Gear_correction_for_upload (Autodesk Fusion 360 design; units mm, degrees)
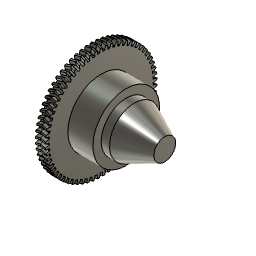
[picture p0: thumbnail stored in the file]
derived_base_feature "Derived Base Feature1"
derived_base_feature "Derived Base Feature2" bodies "Gear_roll_holder"
derived_base_feature "Derived Base Feature1" bodies "Body1"
derived_base_feature "Derived Base Feature1" bodies "Body1"
derived_base_feature "Derived Base Feature1" bodies "S2_L_Pin"
sketch "Sketch1" plane through (0, 0, 0) normal (0, 0, 1) x axis (1, 0, 0)
  line L1 (-12, -33.5) -> (-12, 33.5)
  line L2 (3, 32) -> (3, -32)
  vertical L1
  vertical L2
sketch "Sketch1" plane through (0, 0, 0) normal (0, 0, 1) x axis (1, 0, 0)
  curve K1 (33.4964, -0.4902) -> (31.4518, -0.9347)
  curve K2 (33.4964, 0.4902) -> (31.4518, 0.9347)
  curve K3 (31.4518, -0.9347) -> (31.4509, -0.9347)
  curve K4 (31.4518, 0.9347) -> (31.4509, 0.9347)
  line L1 (31.4509, -0.9347) -> (0, 0)
  line L2 (31.4509, 0.9347) -> (0, 0)
  arc A1 centre (0, 0) radius 33.5 clockwise from (33.4964, 0.4902) to (33.4964, -0.4902)
sketch "Sketch2" plane through (0, 0, 0) normal (0, 0, 1) x axis (1, 0, 0)
  circle C1 centre (0, 0) radius 31.25
extrude "Extrude1" new body sketch "Sketch2" along normal blind 6 bodies "Gear_RH_65T_Wrong"
extrude "Extrude2" new body sketch "Sketch1" along normal blind 6
circular_pattern "C-Pattern1" countU 65 TotalAngle 360
combine "Combine1"
sketch "Sketch3" plane through (0, 0, 0) normal (0, 0, 1) x axis (1, 0, 0)
  curve K1 (51.2476, 0) -> (0, 0)
  curve K2 (51.2476, 3) -> (51.2476, 0)
  curve K3 (0, 3) -> (51.2476, 3)
  curve K4 (0, 0) -> (0, 3)
  perpendicular K1 K2
  parallel K1 K3
  parallel K2 K4
position "Position2"
sketch "Sketch2" plane through (0, 0, 0) normal (0, 1, 0) x axis (0, 0, 1)
  line L1 (37.12, -11) -> (104.1, -12)
  line L2 (38.6, 3) -> (102.6, 3)
  horizontal L2
sketch "Sketch1" plane through (0, 0, 0) normal (0, 0, 1) x axis (1, 0, 0)
  curve K1 (32.4963, -0.4892) -> (30.4833, -0.9294)
  curve K2 (32.4963, 0.4892) -> (30.4833, 0.9294)
  curve K3 (30.4833, -0.9294) -> (30.4825, -0.9293)
  curve K4 (30.4833, 0.9294) -> (30.4825, 0.9293)
  line L1 (30.4825, -0.9293) -> (0, 0)
  line L2 (30.4825, 0.9293) -> (0, 0)
  line L3 (0, 0) -> (0, 0)
  line L4 (0, 0) -> (0, 0)
  arc A1 centre (0, 0) radius 32.5 clockwise from (32.4963, 0.4892) to (32.4963, -0.4892)
sketch "Sketch2" plane through (0, 0, 0) normal (0, 0, 1) x axis (1, 0, 0)
  circle C1 centre (0, 0) radius 30.25
extrude "Extrude1" new body sketch "Sketch2" along normal blind 3
sweep "Sweep1" sketch "Sketch1" TwistAngle 1.5 TaperAngle 0
circular_pattern "C-Pattern1" countU 63 TotalAngle 360
combine "Combine1"
work_plane "WorkPlane1" AlongDistance 3
mirror "Mirror1" mirrorStitchTolerance 0.01
combine "Combine2"
sketch "Sketch3" plane through (0, 0, 0) normal (0, 0, 1) x axis (1, 0, 0)
  curve K1 (87.334, 0) -> (0, 0)
  curve K2 (87.334, 3) -> (87.334, 0)
  curve K3 (0, 3) -> (87.334, 3)
  curve K4 (0, 0) -> (0, 3)
  perpendicular K1 K2
  parallel K1 K3
  parallel K2 K4
position "Position3"
sketch "Sketch3" plane through (0, 0, 0) normal (0, -1, 0) x axis (0, 0, 1)
  line L1 (38.09, 18) -> (103.0863, 18)
  line L2 (38.6, -3) -> (102.6, -3)
  horizontal L1
  horizontal L2
sketch "Sketch1" plane through (0, 0, 0) normal (0, 0, 1) x axis (1, 0, 0)
  curve K1 (32.9964, -0.4897) -> (30.9676, -0.932)
  curve K2 (32.9964, 0.4897) -> (30.9676, 0.932)
  curve K3 (30.9676, -0.932) -> (30.9667, -0.932)
  curve K4 (30.9676, 0.932) -> (30.9667, 0.932)
  line L1 (30.9667, -0.932) -> (0, 0)
  line L2 (30.9667, 0.932) -> (0, 0)
  line L3 (0, 0) -> (0, 0)
  line L4 (0, 0) -> (0, 0)
  arc A1 centre (0, 0) radius 33 clockwise from (32.9964, 0.4897) to (32.9964, -0.4897)
sketch "Sketch2" plane through (0, 0, 0) normal (0, 0, 1) x axis (1, 0, 0)
  circle C1 centre (0, 0) radius 30.75
extrude "Extrude1" new body sketch "Sketch2" along normal blind 3 bodies "Gear_RH_64T"
sweep "Sweep1" sketch "Sketch1" TwistAngle 1.4 TaperAngle 0
circular_pattern "C-Pattern1" countU 64 TotalAngle 360
combine "Combine1"
work_plane "WorkPlane1" AlongDistance 3
mirror "Mirror1" mirrorStitchTolerance 0.01
combine "Combine2"
sketch "Sketch3" plane through (0, 0, 0) normal (0, 0, 1) x axis (1, 0, 0)
  curve K1 (87.334, 0) -> (0, 0)
  curve K2 (87.334, 3) -> (87.334, 0)
  curve K3 (0, 3) -> (87.334, 3)
  curve K4 (0, 0) -> (0, 3)
  perpendicular K1 K2
  parallel K1 K3
  parallel K2 K4
position "Position4"
sketch "Sketch4" plane through (0, 0, 0) normal (0, 1, 0) x axis (1, 0, 0)
  line L1 (-32.4586, -37.1192) -> (-32.5, -104.1)
  line L2 (-25, -37.6) -> (-25, -103.6)
  line L3 (-18, -38.1) -> (-18, -103.1)
  line L4 (3, -38.6) -> (3, -102.6)
  vertical L2
  vertical L3
  vertical L4
position "Position6"
combine "Combine2"
combine "Combine3"
sketch "Sketch1" plane through (0, 0, 0) normal (0, 0, 1) x axis (1, 0, 0)
  curve K1 (33.4964, -0.4902) -> (31.4518, -0.9347)
  curve K2 (33.4964, 0.4902) -> (31.4518, 0.9347)
  curve K3 (31.4518, -0.9347) -> (31.4509, -0.9347)
  curve K4 (31.4518, 0.9347) -> (31.4509, 0.9347)
  line L1 (31.4509, -0.9347) -> (0, 0)
  line L2 (31.4509, 0.9347) -> (0, 0)
  line L3 (0, 0) -> (0, 0)
  line L4 (0, 0) -> (0, 0)
  arc A1 centre (0, 0) radius 33.5 clockwise from (33.4964, 0.4902) to (33.4964, -0.4902)
sketch "Sketch2" plane through (0, 0, 0) normal (0, 0, 1) x axis (1, 0, 0)
  circle C1 centre (0, 0) radius 31.25
extrude "Extrude1" new body sketch "Sketch2" along normal blind 3
sweep "Sweep1" sketch "Sketch1" TwistAngle 1.4 TaperAngle 0
circular_pattern "C-Pattern1" countU 65 TotalAngle 360
combine "Combine1"
work_plane "WorkPlane1" AlongDistance 3
mirror "Mirror1" mirrorStitchTolerance 0.01
combine "Combine2"
sketch "Sketch3" plane through (0, 0, 0) normal (0, 0, 1) x axis (1, 0, 0)
  curve K1 (87.334, 0) -> (0, 0)
  curve K2 (87.334, 3) -> (87.334, 0)
  curve K3 (0, 3) -> (87.334, 3)
  curve K4 (0, 0) -> (0, 3)
  perpendicular K1 K2
  parallel K1 K3
  parallel K2 K4
position "Position7"
sketch "Sketch5" plane through (0, 0, 0) normal (0, 1, 0) x axis (0, 0, 1)
combine "Combine3"
position "Position8"
combine "Combine4"
remove_instance "RemoveInstance1"
remove_instance "RemoveInstance2"
remove_instance "RemoveInstance3"
remove_instance "RemoveInstance4"
remove_instance "RemoveInstance5"
remove_instance "RemoveInstance6"
position "Position5"
combine "Combine3"
combine "Combine4"
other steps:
create_component "CreateComponent1"
create_component "CreateComponent2"
create_component "CreateComponent3"
create_component "CreateComponent8"
create_component "CreateComponent9"
create_component "CreateComponent10"
create_component "CreateComponent11"
named bodies: "Gear_roll_holder", "S2_L_Pin", "Body1", "Gear_RH_65T_Wrong", "Gear_RH_64T"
